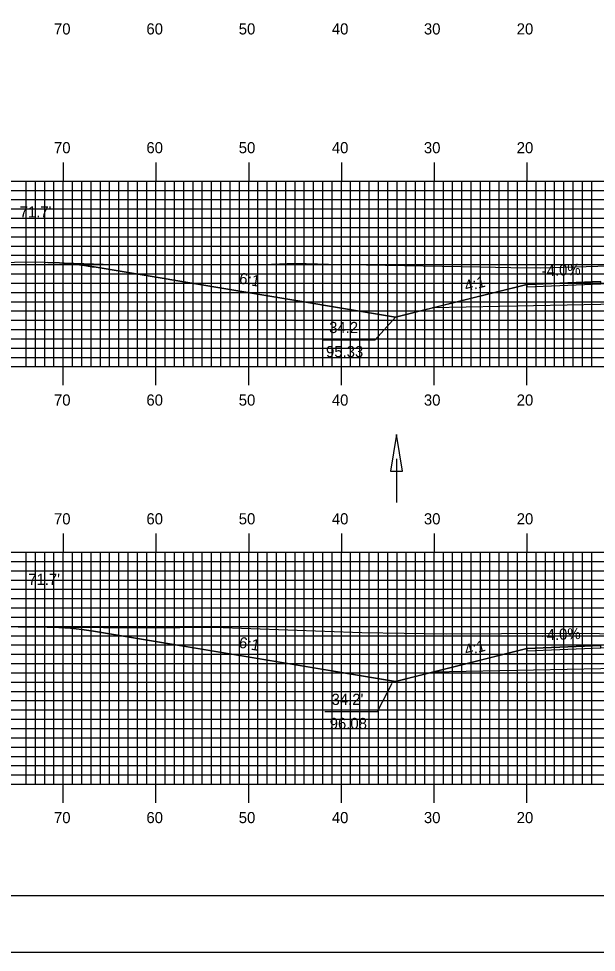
# Model space of a CAD drawing. Extents: x 1775170 to 1775514, y 442591 to 442811.
# Drawn here: x 1775261.4 to 1775323.7, y 442590.5 to 442691.2 of the extents above; entities that cross this region are included whole.
import ezdxf

# ---------------------------------------------------------------- set-up
doc = ezdxf.new("R2010")
doc.units = 0
for name, color, linetype in [('ANNOTATION', 7, 'Continuous'), ('BORDER', 7, 'Continuous'), ('D_Drainage_Ditch_Line', 7, 'Continuous'), ('D_Roadway_Centerline', 7, 'Continuous'), ('D_Roadway_Edge_Shoulder', 7, 'Continuous'), ('D_Roadway_SlopeLines', 7, 'Continuous'), ('D_Roadway_SubGrade', 7, 'Continuous'), ('D_Text_Standard', 7, 'Continuous'), ('H_V ANNOTATION', 7, 'Continuous'), ('MAJOR', 7, 'Continuous'), ('MINOR', 7, 'Continuous'), ('PLOT BOUNDARY', 7, 'Continuous'), ('S_Roadway_Centerline', 7, 'Continuous')]:
    doc.layers.add(name, color=color, linetype=linetype)

msp = doc.modelspace()

# ---------------------------------------------------------------- linework, layer by layer
at = {"layer": 'ANNOTATION'}
for points in [[(1775294.15, 442656.56), (1775299.84, 442656.56), (1775302.02, 442658.99)], [(1775294.4, 442616.49), (1775300.09, 442616.49), (1775301.66, 442619.55)]]:
    msp.add_lwpolyline(points, dxfattribs=at)
at = {"layer": 'BORDER'}
msp.add_lwpolyline([(1775186.6, 442596.67), (1775506.6, 442596.67), (1775506.6, 442806.67), (1775186.6, 442806.67)], close=True, dxfattribs=at)
at = {"layer": 'D_Drainage_Ditch_Line'}
msp.add_line((1775302.14, 442643.73), (1775302.14, 442639.03), dxfattribs=at)
msp.add_lwpolyline([(1775301.48, 442642.42), (1775302.79, 442642.42), (1775302.14, 442646.36)], close=True, dxfattribs=at)
at = {"layer": 'D_Roadway_Centerline'}
for points in [[(1775264.53, 442664.91), (1775265.12, 442664.88), (1775265.78, 442664.85), (1775266.76, 442664.76), (1775267.03, 442664.74), (1775268.28, 442664.59), (1775269.31, 442664.44), (1775269.53, 442664.41), (1775302.02, 442658.99), (1775306.02, 442659.99), (1775311.93, 442661.47), (1775316.2, 442662.53), (1775324.2, 442662.85)], [(1775264.47, 442625.6), (1775264.92, 442625.59), (1775265.72, 442625.57), (1775266.97, 442625.48), (1775268.22, 442625.35), (1775269.47, 442625.17), (1775288.26, 442622.03), (1775302.02, 442619.74), (1775304.72, 442620.41), (1775306.02, 442620.74), (1775316.2, 442623.28), (1775324.2, 442623.6)]]:
    msp.add_lwpolyline(points, dxfattribs=at)
at = {"layer": 'D_Roadway_Edge_Shoulder'}
for points in [[(1775324.2, 442662.85), (1775316.2, 442662.53), (1775316.2, 442662.28), (1775324.2, 442662.6)], [(1775324.2, 442623.6), (1775316.2, 442623.28), (1775316.2, 442623.03), (1775324.2, 442623.35)]]:
    msp.add_lwpolyline(points, close=True, dxfattribs=at)
at = {"layer": 'D_Roadway_SlopeLines'}
for points in [[(1775302.02, 442658.99), (1775269.53, 442664.41), (1775268.28, 442664.59), (1775267.03, 442664.74), (1775265.78, 442664.85), (1775264.53, 442664.91)], [(1775316.2, 442662.53), (1775302.02, 442658.99)], [(1775302.02, 442619.74), (1775269.47, 442625.17), (1775268.22, 442625.35), (1775266.97, 442625.48), (1775265.72, 442625.57), (1775264.47, 442625.6)], [(1775316.2, 442623.28), (1775302.02, 442619.74)]]:
    msp.add_lwpolyline(points, dxfattribs=at)
at = {"layer": 'D_Roadway_SubGrade'}
for points in [[(1775324.2, 442660.35), (1775306.02, 442659.99), (1775316.2, 442662.53), (1775316.2, 442662.28), (1775324.2, 442662.6), (1775336.2, 442662.84), (1775348.2, 442662.6), (1775356.2, 442662.28), (1775356.2, 442662.53), (1775366.37, 442659.99), (1775348.2, 442660.35), (1775336.2, 442660.59)], [(1775324.2, 442621.1), (1775306.02, 442620.74), (1775316.2, 442623.28), (1775316.2, 442623.03), (1775324.2, 442623.35), (1775336.2, 442623.59), (1775348.2, 442623.35), (1775356.2, 442623.03), (1775356.2, 442623.28), (1775366.37, 442620.74), (1775348.2, 442621.1), (1775336.2, 442621.34)]]:
    msp.add_lwpolyline(points, close=True, dxfattribs=at)
at = {"layer": 'MAJOR'}
for p, q in [((1775266.2, 442675.67), (1775266.2, 442673.67)), ((1775276.2, 442675.67), (1775276.2, 442673.67)), ((1775286.2, 442675.67), (1775286.2, 442673.67)), ((1775296.2, 442675.67), (1775296.2, 442673.67)), ((1775306.2, 442675.67), (1775306.2, 442673.67)), ((1775316.2, 442675.67), (1775316.2, 442673.67)), ((1775196.2, 442673.67), (1775476.2, 442673.67)), ((1775196.2, 442673.67), (1775476.2, 442673.67)), ((1775266.2, 442653.67), (1775266.2, 442673.67)), ((1775276.2, 442653.67), (1775276.2, 442673.67)), ((1775286.2, 442653.67), (1775286.2, 442673.67)), ((1775296.2, 442653.67), (1775296.2, 442673.67)), ((1775306.2, 442653.67), (1775306.2, 442673.67)), ((1775316.2, 442653.67), (1775316.2, 442673.67)), ((1775196.2, 442668.67), (1775476.2, 442668.67)), ((1775196.2, 442663.67), (1775476.2, 442663.67)), ((1775196.2, 442658.67), (1775476.2, 442658.67)), ((1775196.2, 442653.67), (1775476.2, 442653.67)), ((1775196.2, 442653.67), (1775476.2, 442653.67)), ((1775266.2, 442651.66), (1775266.2, 442653.67)), ((1775276.2, 442651.66), (1775276.2, 442653.67)), ((1775286.2, 442651.66), (1775286.2, 442653.67)), ((1775296.2, 442651.66), (1775296.2, 442653.67)), ((1775306.2, 442651.66), (1775306.2, 442653.67)), ((1775316.2, 442651.66), (1775316.2, 442653.67)), ((1775266.2, 442635.67), (1775266.2, 442633.67)), ((1775276.2, 442635.67), (1775276.2, 442633.67)), ((1775286.2, 442635.67), (1775286.2, 442633.67)), ((1775296.2, 442635.67), (1775296.2, 442633.67)), ((1775306.2, 442635.67), (1775306.2, 442633.67)), ((1775316.2, 442635.67), (1775316.2, 442633.67)), ((1775196.2, 442633.67), (1775476.2, 442633.67)), ((1775196.2, 442633.67), (1775476.2, 442633.67)), ((1775266.2, 442608.67), (1775266.2, 442633.67)), ((1775276.2, 442608.67), (1775276.2, 442633.67)), ((1775286.2, 442608.67), (1775286.2, 442633.67)), ((1775296.2, 442608.67), (1775296.2, 442633.67)), ((1775306.2, 442608.67), (1775306.2, 442633.67)), ((1775316.2, 442608.67), (1775316.2, 442633.67)), ((1775196.2, 442628.67), (1775476.2, 442628.67)), ((1775196.2, 442623.67), (1775476.2, 442623.67)), ((1775196.2, 442618.67), (1775476.2, 442618.67)), ((1775196.2, 442613.67), (1775476.2, 442613.67)), ((1775196.2, 442608.67), (1775476.2, 442608.67)), ((1775196.2, 442608.67), (1775476.2, 442608.67)), ((1775266.2, 442606.66), (1775266.2, 442608.67)), ((1775276.2, 442606.66), (1775276.2, 442608.67)), ((1775286.2, 442606.66), (1775286.2, 442608.67)), ((1775296.2, 442606.66), (1775296.2, 442608.67)), ((1775306.2, 442606.66), (1775306.2, 442608.67)), ((1775316.2, 442606.66), (1775316.2, 442608.67))]:
    msp.add_line(p, q, dxfattribs=at)
at = {"layer": 'MINOR'}
for p, q in [((1775262.2, 442653.67), (1775262.2, 442673.67)), ((1775263.2, 442653.67), (1775263.2, 442673.67)), ((1775264.2, 442653.67), (1775264.2, 442673.67)), ((1775265.2, 442653.67), (1775265.2, 442673.67)), ((1775267.2, 442653.67), (1775267.2, 442673.67)), ((1775268.2, 442653.67), (1775268.2, 442673.67)), ((1775269.2, 442653.67), (1775269.2, 442673.67)), ((1775270.2, 442653.67), (1775270.2, 442673.67)), ((1775271.2, 442653.67), (1775271.2, 442673.67)), ((1775272.2, 442653.67), (1775272.2, 442673.67)), ((1775273.2, 442653.67), (1775273.2, 442673.67)), ((1775274.2, 442653.67), (1775274.2, 442673.67)), ((1775275.2, 442653.67), (1775275.2, 442673.67)), ((1775277.2, 442653.67), (1775277.2, 442673.67)), ((1775278.2, 442653.67), (1775278.2, 442673.67)), ((1775279.2, 442653.67), (1775279.2, 442673.67)), ((1775280.2, 442653.67), (1775280.2, 442673.67)), ((1775281.2, 442653.67), (1775281.2, 442673.67)), ((1775282.2, 442653.67), (1775282.2, 442673.67)), ((1775283.2, 442653.67), (1775283.2, 442673.67)), ((1775284.2, 442653.67), (1775284.2, 442673.67)), ((1775285.2, 442653.67), (1775285.2, 442673.67)), ((1775287.2, 442653.67), (1775287.2, 442673.67)), ((1775288.2, 442653.67), (1775288.2, 442673.67)), ((1775289.2, 442653.67), (1775289.2, 442673.67)), ((1775290.2, 442653.67), (1775290.2, 442673.67)), ((1775291.2, 442653.67), (1775291.2, 442673.67)), ((1775292.2, 442653.67), (1775292.2, 442673.67)), ((1775293.2, 442653.67), (1775293.2, 442673.67)), ((1775294.2, 442653.67), (1775294.2, 442673.67)), ((1775295.2, 442653.67), (1775295.2, 442673.67)), ((1775297.2, 442653.67), (1775297.2, 442673.67)), ((1775298.2, 442653.67), (1775298.2, 442673.67)), ((1775299.2, 442653.67), (1775299.2, 442673.67)), ((1775300.2, 442653.67), (1775300.2, 442673.67)), ((1775301.2, 442653.67), (1775301.2, 442673.67)), ((1775302.2, 442653.67), (1775302.2, 442673.67)), ((1775303.2, 442653.67), (1775303.2, 442673.67)), ((1775304.2, 442653.67), (1775304.2, 442673.67)), ((1775305.2, 442653.67), (1775305.2, 442673.67)), ((1775307.2, 442653.67), (1775307.2, 442673.67)), ((1775308.2, 442653.67), (1775308.2, 442673.67)), ((1775309.2, 442653.67), (1775309.2, 442673.67)), ((1775310.2, 442653.67), (1775310.2, 442673.67)), ((1775311.2, 442653.67), (1775311.2, 442673.67)), ((1775312.2, 442653.67), (1775312.2, 442673.67)), ((1775313.2, 442653.67), (1775313.2, 442673.67)), ((1775314.2, 442653.67), (1775314.2, 442673.67)), ((1775315.2, 442653.67), (1775315.2, 442673.67)), ((1775317.2, 442653.67), (1775317.2, 442673.67)), ((1775318.2, 442653.67), (1775318.2, 442673.67)), ((1775319.2, 442653.67), (1775319.2, 442673.67)), ((1775320.2, 442653.67), (1775320.2, 442673.67)), ((1775321.2, 442653.67), (1775321.2, 442673.67)), ((1775322.2, 442653.67), (1775322.2, 442673.67)), ((1775323.2, 442653.67), (1775323.2, 442673.67)), ((1775196.2, 442672.67), (1775476.2, 442672.67)), ((1775196.2, 442671.67), (1775476.2, 442671.67)), ((1775196.2, 442670.67), (1775476.2, 442670.67)), ((1775196.2, 442669.67), (1775476.2, 442669.67)), ((1775196.2, 442667.67), (1775476.2, 442667.67)), ((1775196.2, 442666.67), (1775476.2, 442666.67)), ((1775196.2, 442665.67), (1775476.2, 442665.67)), ((1775196.2, 442664.67), (1775476.2, 442664.67)), ((1775196.2, 442662.67), (1775476.2, 442662.67)), ((1775196.2, 442661.67), (1775476.2, 442661.67)), ((1775196.2, 442660.67), (1775476.2, 442660.67)), ((1775196.2, 442659.67), (1775476.2, 442659.67)), ((1775196.2, 442657.67), (1775476.2, 442657.67)), ((1775196.2, 442656.67), (1775476.2, 442656.67)), ((1775196.2, 442655.67), (1775476.2, 442655.67)), ((1775196.2, 442654.67), (1775476.2, 442654.67)), ((1775262.2, 442608.67), (1775262.2, 442633.67)), ((1775263.2, 442608.67), (1775263.2, 442633.67)), ((1775264.2, 442608.67), (1775264.2, 442633.67)), ((1775265.2, 442608.67), (1775265.2, 442633.67)), ((1775267.2, 442608.67), (1775267.2, 442633.67)), ((1775268.2, 442608.67), (1775268.2, 442633.67)), ((1775269.2, 442608.67), (1775269.2, 442633.67)), ((1775270.2, 442608.67), (1775270.2, 442633.67)), ((1775271.2, 442608.67), (1775271.2, 442633.67)), ((1775272.2, 442608.67), (1775272.2, 442633.67)), ((1775273.2, 442608.67), (1775273.2, 442633.67)), ((1775274.2, 442608.67), (1775274.2, 442633.67)), ((1775275.2, 442608.67), (1775275.2, 442633.67)), ((1775277.2, 442608.67), (1775277.2, 442633.67)), ((1775278.2, 442608.67), (1775278.2, 442633.67)), ((1775279.2, 442608.67), (1775279.2, 442633.67)), ((1775280.2, 442608.67), (1775280.2, 442633.67)), ((1775281.2, 442608.67), (1775281.2, 442633.67)), ((1775282.2, 442608.67), (1775282.2, 442633.67)), ((1775283.2, 442608.67), (1775283.2, 442633.67)), ((1775284.2, 442608.67), (1775284.2, 442633.67)), ((1775285.2, 442608.67), (1775285.2, 442633.67)), ((1775287.2, 442608.67), (1775287.2, 442633.67)), ((1775288.2, 442608.67), (1775288.2, 442633.67)), ((1775289.2, 442608.67), (1775289.2, 442633.67)), ((1775290.2, 442608.67), (1775290.2, 442633.67)), ((1775291.2, 442608.67), (1775291.2, 442633.67)), ((1775292.2, 442608.67), (1775292.2, 442633.67)), ((1775293.2, 442608.67), (1775293.2, 442633.67)), ((1775294.2, 442608.67), (1775294.2, 442633.67)), ((1775295.2, 442608.67), (1775295.2, 442633.67)), ((1775297.2, 442608.67), (1775297.2, 442633.67)), ((1775298.2, 442608.67), (1775298.2, 442633.67)), ((1775299.2, 442608.67), (1775299.2, 442633.67)), ((1775300.2, 442608.67), (1775300.2, 442633.67)), ((1775301.2, 442608.67), (1775301.2, 442633.67)), ((1775302.2, 442608.67), (1775302.2, 442633.67)), ((1775303.2, 442608.67), (1775303.2, 442633.67)), ((1775304.2, 442608.67), (1775304.2, 442633.67)), ((1775305.2, 442608.67), (1775305.2, 442633.67)), ((1775307.2, 442608.67), (1775307.2, 442633.67)), ((1775308.2, 442608.67), (1775308.2, 442633.67)), ((1775309.2, 442608.67), (1775309.2, 442633.67)), ((1775310.2, 442608.67), (1775310.2, 442633.67)), ((1775311.2, 442608.67), (1775311.2, 442633.67)), ((1775312.2, 442608.67), (1775312.2, 442633.67)), ((1775313.2, 442608.67), (1775313.2, 442633.67)), ((1775314.2, 442608.67), (1775314.2, 442633.67)), ((1775315.2, 442608.67), (1775315.2, 442633.67)), ((1775317.2, 442608.67), (1775317.2, 442633.67)), ((1775318.2, 442608.67), (1775318.2, 442633.67)), ((1775319.2, 442608.67), (1775319.2, 442633.67)), ((1775320.2, 442608.67), (1775320.2, 442633.67)), ((1775321.2, 442608.67), (1775321.2, 442633.67)), ((1775322.2, 442608.67), (1775322.2, 442633.67)), ((1775323.2, 442608.67), (1775323.2, 442633.67)), ((1775196.2, 442632.67), (1775476.2, 442632.67)), ((1775196.2, 442631.67), (1775476.2, 442631.67)), ((1775196.2, 442630.67), (1775476.2, 442630.67)), ((1775196.2, 442629.67), (1775476.2, 442629.67)), ((1775196.2, 442627.67), (1775476.2, 442627.67)), ((1775196.2, 442626.67), (1775476.2, 442626.67)), ((1775196.2, 442625.67), (1775476.2, 442625.67)), ((1775196.2, 442624.67), (1775476.2, 442624.67)), ((1775196.2, 442622.67), (1775476.2, 442622.67)), ((1775196.2, 442621.67), (1775476.2, 442621.67)), ((1775196.2, 442620.67), (1775476.2, 442620.67)), ((1775196.2, 442619.67), (1775476.2, 442619.67)), ((1775196.2, 442617.67), (1775476.2, 442617.67)), ((1775196.2, 442616.67), (1775476.2, 442616.67)), ((1775196.2, 442615.67), (1775476.2, 442615.67)), ((1775196.2, 442614.67), (1775476.2, 442614.67)), ((1775196.2, 442612.67), (1775476.2, 442612.67)), ((1775196.2, 442611.67), (1775476.2, 442611.67)), ((1775196.2, 442610.67), (1775476.2, 442610.67)), ((1775196.2, 442609.67), (1775476.2, 442609.67))]:
    msp.add_line(p, q, dxfattribs=at)
at = {"layer": 'PLOT BOUNDARY'}
msp.add_lwpolyline([(1775170.41, 442590.55), (1775510.41, 442590.55), (1775510.41, 442810.55), (1775170.41, 442810.55)], close=True, dxfattribs=at)
at = {"layer": 'S_Roadway_Centerline'}
for points in [[(1775250, 442664.76), (1775263.15, 442664.96), (1775272.62, 442664.63), (1775287.79, 442664.69), (1775291.22, 442664.83), (1775294.81, 442664.71), (1775311.18, 442664.42), (1775314.48, 442664.34), (1775317.68, 442664.33), (1775338.68, 442664.93), (1775341.71, 442664.94), (1775358.47, 442664.01), (1775360.64, 442663.9), (1775363.21, 442663.82), (1775373.11, 442663.8), (1775382.13, 442663.57), (1775383.72, 442663.54), (1775407.44, 442663.17)], [(1775261.35, 442625.63), (1775275.14, 442625.51), (1775282.45, 442625.59), (1775298.39, 442625.03), (1775307.55, 442624.86), (1775313.47, 442624.9), (1775319.95, 442624.93), (1775332.28, 442624.82), (1775343.45, 442624.33), (1775348.41, 442624.44), (1775353.96, 442623.83), (1775360.21, 442623.19), (1775365.65, 442622.41), (1775378.64, 442621.86), (1775382.79, 442622.06), (1775387.02, 442621.59), (1775400.77, 442621.77)]]:
    msp.add_lwpolyline(points, dxfattribs=at)

# ---------------------------------------------------------------- texts
at = {"layer": 'ANNOTATION'}
for s, rotation, p in [('-4.0%', 2.2905, (1775317.83, 442663.4)), ('6:1', 350.5378, (1775285.11, 442662.64)), ('4:1', 14.0392, (1775309.65, 442661.76)), ('-4.0%', 2.2909, (1775317.83, 442624.15)), ('6:1', 350.5374, (1775285.08, 442623.39)), ('4:1', 14.0382, (1775309.65, 442622.51))]:
    msp.add_text(s, height=1.2, rotation=rotation, dxfattribs=at).set_placement(p)
for s, p in [("34.2'", (1775294.88, 442657.29)), ('95.33', (1775294.54, 442654.69)), ("34.2'", (1775295.14, 442617.21)), ('96.08', (1775294.94, 442614.61))]:
    msp.add_text(s, height=1.2, dxfattribs=at).set_placement(p)
at = {"layer": 'D_Text_Standard'}
for p in [(1775261.5, 442669.75), (1775262.42, 442630.14)]:
    msp.add_text("71.7'", height=1.2, dxfattribs=at).set_placement(p)
at = {"layer": 'H_V ANNOTATION'}
for s, p in [('70', (1775265.2, 442689.47)), ('60', (1775275.17, 442689.47)), ('50', (1775285.13, 442689.47)), ('40', (1775295.17, 442689.47)), ('30', (1775305.1, 442689.47)), ('20', (1775315.11, 442689.47)), ('70', (1775265.2, 442676.67)), ('60', (1775275.17, 442676.67)), ('50', (1775285.13, 442676.67)), ('40', (1775295.17, 442676.67)), ('30', (1775305.1, 442676.67)), ('20', (1775315.11, 442676.67)), ('70', (1775265.2, 442649.47)), ('60', (1775275.17, 442649.47)), ('50', (1775285.13, 442649.47)), ('40', (1775295.17, 442649.47)), ('30', (1775305.1, 442649.47)), ('20', (1775315.11, 442649.47)), ('70', (1775265.2, 442636.67)), ('60', (1775275.17, 442636.67)), ('50', (1775285.13, 442636.67)), ('40', (1775295.17, 442636.67)), ('30', (1775305.1, 442636.67)), ('20', (1775315.11, 442636.67)), ('70', (1775265.2, 442604.47)), ('60', (1775275.17, 442604.47)), ('50', (1775285.13, 442604.47)), ('40', (1775295.17, 442604.47)), ('30', (1775305.1, 442604.47)), ('20', (1775315.11, 442604.47))]:
    msp.add_text(s, height=1.2, dxfattribs=at).set_placement(p)

doc.saveas('drawing.dxf')
